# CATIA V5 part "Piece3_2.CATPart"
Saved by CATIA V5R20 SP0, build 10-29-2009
Part number: Pièce3
Bounding box of the stored display mesh (mm): x -5 to 0, y 23.622 to 46.174, z -18.562 to 20.74
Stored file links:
  C:\Users\ASUS\Desktop\Think Motion IAO\Piece3_2.CATPart
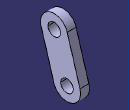
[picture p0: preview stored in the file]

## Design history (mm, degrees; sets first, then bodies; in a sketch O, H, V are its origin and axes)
Body1 (main body)
  Plane1: stored without definition
  Point1 "Point.B": stored without definition
  Point2 "Point.C": stored without definition
  Point3 "Point.C": stored without definition
  Point4 "Point.B": stored without definition
  Sketch1 on Plane1, origin (0, 0, 0), H (0, 1, 0), V (0, 0, 1)
    point P1 (25.8403, 15.5034)
    construction line L1 (38.4908, -10.8837) -> (31.305, 13.0613)
    line L2 (31.1311, -13.0923) -> (23.9452, 10.8527)
    line L3 (38.6648, 15.27) -> (45.8506, -8.675)
    arc A1 centre (31.305, 13.0613) radius 7.684 from (23.9452, 10.8527) to (38.6648, 15.27) cw
    arc A2 centre (38.4908, -10.8837) radius 7.684 from (45.8506, -8.675) to (31.1311, -13.0923) cw
    reference projected point E1 (31.305, 13.0613) from Point1
    reference projected point E2 (38.4908, -10.8837) from Point2
    circle A3 centre (38.4908, -10.8837) radius 3.5
    reference projected point E3 (38.4908, -10.8837) from Point3
    circle A4 centre (31.305, 13.0613) radius 3.5
    reference projected point E4 (31.305, 13.0613) from Point4
    distance L1 L2 = 7.684
    radius A3 = 3.5
    radius A4 = 3.5
    tangency: A1 L2, A2 L2, A1 L3, A2 L3
    concentricity: A1 E1, A2 E2, A3 E3, A4 E4
  Pad1: profile Sketch1, direction (1, 0, 0), length -5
